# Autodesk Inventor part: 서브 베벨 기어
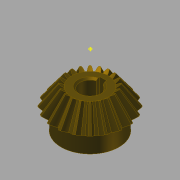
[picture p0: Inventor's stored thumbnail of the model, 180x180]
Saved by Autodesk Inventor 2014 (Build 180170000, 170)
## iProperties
Created: 2014-10
Part Number: 서브 베벨 기어
Material: 강철, 탄소
Document SubType Name: Modeling
Designer: KYOUNG IL JANG
Categories: <?xml version="1.0" encoding="UTF-16"?> <MemberInstance><Categories><FamilyTemplate><FamilyTemplateParameter ValueType="xs:double" Id="1" ObjectReferenceKey="da
Mass: 135.037 g
Surface Area: 63.6518 cm^2
Volume: 17.1585 cm^3
Density: 7.87 g/cm^3
Appearance: 얼룩무늬
CustomPartVersion: 1
Author: SeoGD™ [www.esajin.kr]
Revision Number: 1
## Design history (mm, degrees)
node "맨 위 점"
node "메쉬 평면2"
sketch "톱니 본체 스케치"
  geometry: L1 (0, 0)-(18.003, -31.331); L2 (18.003, -31.331)-(21.664, -28.891); L3 (21.664, -28.891)-(0, 0); L4 (20, -30)-(0, 0); L5 (10.813, -18.818)-(13.012, -17.352); L6 (18.003, -31.331)-(10.813, -18.818); L7 (21.664, -28.891)-(13.012, -17.352); L8 (0, -39.387)-(0, 6.564) reference; L9 (0, -30)-(21.664, -30)
  constraints: 16 end point, 4 point on line, 3 perpendicular, 2 collinear, 1 horizontal alignment, 1 vertical alignment
  dimensions: "d0" = 40 diameter of L4.start L8 (= da_de); "d1" = 36.00616 diameter of L1.end L8 (= da_dfe); "d2" = 43.3282 diameter of L2.end L8 (= da_dae); "d3" = 14.4 distance between parallel lines of L2 L5 (= da_b); "d4" = 28.8906 vertical distance of L2.end L1.start (= da_ve)
revolve "톱니 본체" sketch "톱니 본체 스케치" stored, may be unused: angle "d5" = 90 deg
node "시작점"
node "톱니 평면"
sketch "시작 스케치"
  geometry: L1 (0, -23.505)-(0, 10.645) reference; L2 (-0.834, -2.928)-(0.834, -2.928); A1 r 8.898 centre (-9.698, -3.713) between (-0.834, -2.928) and (-3.903, 3.04); A2 r 8.898 centre (9.698, -3.713) between (3.903, 3.04) and (0.834, -2.928); A3 r 27.357 centre (0, -24.037) between (3.903, 3.04) and (-3.903, 3.04); 1 further point
  constraints: 6 point on circle, 3 centre point, 3 symmetric about line, 2 end point, 1 coincident, 1 perpendicular, 1 other
  dimensions: "d7" = 8.89846 radius of A1 (= fd_rr); "d8" = 9.69794 horizontal distance of point (0, -24.037) A1.centre (= fd_x); "d9" = 20.32439 vertical distance of point (0, -24.037) A1.centre (= fd_y); "d57" = 27.35701 radius of A3 (= 0.5 x fd_dva + 0.3 x da_he); "d58" = 21.10901 distance from line of A3.centre L2 (= 0.5 x fd_dva - 1.12 x da_he)
node "끝점"
  node "끝 평면"
sketch "3D 스케치 오른쪽"
  node "Helical Curve Right" dims "d65" = 229.90621 (computed from da_dm, da_delta, da_beta), "d66" = 31.5, "d67" = 40 (= da_de), "d68" = -5.88003 (= -da_delta), "d69" = 12.16458 (computed from fd_loft, da_delta)
node "끝 평면 오른쪽"
sketch "끝 스케치 오른쪽"
  geometry: L1 (0, -22.649)-(0, 12.15) reference; L2 (-0.497, -1.72)-(0.497, -1.72); A1 r 5.299 centre (-5.775, -2.187) between (-0.497, -1.72) and (-2.324, 1.834); A2 r 5.299 centre (5.775, -2.187) between (2.324, 1.834) and (0.497, -1.72); A3 r 16.291 centre (0, -14.29) between (2.324, 1.834) and (-2.324, 1.834); 1 further point
  constraints: 6 point on circle, 3 centre point, 3 symmetric about line, 2 end point, 1 coincident, 1 perpendicular, 1 other
  dimensions: "d70" = 5.77526 horizontal distance of A3.centre A1.centre (computed from fd_x, fd_ratio); "d71" = 12.10346 vertical distance of point (0, -14.29) A1.centre (computed from fd_y, fd_ratio); "d72" = 5.29916 radius of A1 (computed from fd_rr, fd_ratio); "d73" = 12.57071 distance from line of point (0, -14.29) L2 (computed from d58, fd_ratio); "d74" = 16.29149 radius of A3 (computed from d57, fd_ratio)
feature "로프트 오른쪽" sketch "끝 스케치 오른쪽" dims "d75" = 0, "d77" = 0, "d79" = 0, "d80" = 90 deg, "d85" = 20, "d92" = 90 deg, "d93" = 90 deg, "da_teethtype" = 0 [user parameter]
sketch "3D 스케치 왼쪽"
  node "Helical Curve Left" dims "d26" = 229.90621 (computed from da_dm, da_delta, da_beta), "d27" = 12.16458 (computed from fd_loft, da_delta), "d28" = 40 (= da_de), "d29" = -5.88003 (= -da_delta)
node "끝 평면 왼쪽"
sketch "끝 스케치 왼쪽" dims "d56" = 10.82768 (derived)
  geometry: L1 (0, -35.087)-(0, 18.089) reference; L2 (-0.497, -1.716)-(0.497, -1.716); A1 r 5.299 centre (-5.775, -2.183) between (-0.497, -1.716) and (-2.324, 1.838); A2 r 5.299 centre (5.775, -2.183) between (2.324, 1.838) and (0.497, -1.716); A3 r 16.291 centre (0, -14.287) between (2.324, 1.838) and (-2.324, 1.838); 2 further points; 1 other entity
  constraints: 6 point on circle, 3 centre point, 3 symmetric about line, 2 end point, 1 coincident, 2 other
  dimensions: "d30" = 5.29916 radius of A1 (computed from fd_rr, fd_ratio); "d31" = 5.77526 horizontal distance of point (0, -14.287) A1.centre (computed from fd_x, fd_ratio); "d32" = 12.10346 vertical distance of A1.centre point (0, -14.287) (computed from fd_y, fd_ratio); "d61" = 16.29149 radius of A3 (computed from d57, fd_ratio); "d62" = 12.57071 distance from line of point (0, -14.287) L2 (computed from d58, fd_ratio)
feature "로프트 왼쪽" sketch "끝 스케치 왼쪽" dims "d35" = 0, "d37" = 0, "d39" = 0, "d40" = 90 deg, "d84" = 10, "d90" = 90 deg, "d91" = 90 deg, "da_teethtype" = 0 [user parameter]
sketch "본체 스케치"
  geometry: L1 (0, -35.038)-(0, -19.531) reference; L2 (18.003, -31.331)-(10.813, -18.818) reference; L3 (10.813, -18.818)-(0, -18.818); L4 (18.003, -31.331)-(0, -31.331)
  constraints: 4 end point, 2 perpendicular, 2 point on line
revolve "본체 고정" sketch "본체 스케치" stored, may be unused: angle "d46" = 90 deg
feature "피치 지름" dims angle "d47" = 90 deg
sketch "스케치8"
  geometry: C1 r 17 at (0, 0); 1 further point
  constraints: 1 centre point, 1 coincident
  dimensions: "d94" = 34 diameter of C1
extrude "돌출1" join sketch "스케치8" distance "d95" = 10; taper "d96" = 0 deg
sketch "스케치9"
  geometry: 1 further point
hole "구멍1" sketch "스케치9" at (0, 0) diameter "d97" = 12; stored, may be unused: countersink angle "d101" = 90 deg, drill point angle "d103" = 118 deg; dims "d98" = 6, "d99" = 4, "d100" = 2, "d102" = 8
sketch "스케치10"
  geometry: 1 further point
sketch "스케치11"
  geometry: 1 further point
sketch "스케치12"
  geometry: L1 (-2, 5.657)-(-2, 7.8); L2 (-2, 7.8)-(2, 7.8); L3 (2, 7.8)-(2, 5.657); A1 r 6 centre (0, 0) between (-2, 5.657) and (2, 5.657) reference; 1 further point
  constraints: 6 end point, 2 parallel, 2 point on circle, 1 perpendicular, 1 vertical
  dimensions: "d104" = 4 distance of L1.end L2.end; "d105" = 13.8 dimension on A1 L2
extrude "돌출2" cut sketch "스케치12" stored distance "d106" = 7; taper "d107" = 0 deg
chamfer "모따기1" distance "d108" = 1; stored, may be unused: second distance "d109" = 2, angle "d110" = 45 deg
body "Solid1"
feature "로프트" dims "d17" = 0, "d18" = 90 deg, "d19" = 0, "d20" = 90 deg, "d89" = 0, "da_teethtype" = 0 [user parameter]
pattern_circular "원형 패턴" dims angle "d22" = 360 deg, "d88" = 0, "da_teethtype" = 0 [user parameter]
pattern_circular "원형 패턴 오른쪽" dims angle "d82" = 360 deg, "da_teethtype" = 0 [user parameter]
pattern_circular "원형 패턴 왼쪽" dims angle "d42" = 360 deg, "da_teethtype" = 0 [user parameter]
sketch "끝 스케치"
  geometry: L1 (0, -15.359)-(0, 6.983) reference; L2 (-0.497, -1.72)-(0.497, -1.72); A1 r 5.299 centre (-5.775, -2.187) between (-0.497, -1.72) and (-2.324, 1.834); A2 r 5.299 centre (5.775, -2.187) between (2.324, 1.834) and (0.497, -1.72); A3 r 16.291 centre (0, -14.29) between (2.324, 1.834) and (-2.324, 1.834); 1 further point
  constraints: 6 point on circle, 3 centre point, 3 symmetric about line, 2 end point, 1 coincident, 1 other
  dimensions: "d12" = 5.29916 radius of A1 (computed from fd_rr, fd_ratio); "d15" = 5.77526 horizontal distance of A1.centre point (0, -14.29) (computed from fd_x, fd_ratio); "d16" = 12.10346 vertical distance of A1.centre point (0, -14.29) (computed from fd_y, fd_ratio); "d59" = 16.29149 radius of A3 (computed from d57, fd_ratio); "d60" = 12.57071 distance from line of A3.centre L2 (computed from d58, fd_ratio)
sketch "Sketch6"
  geometry: L1 (20, -30)-(0, 0) reference; L2 (0, -37.8)-(0, 6.3) reference
body "Srf1"
other parameters: "da_b" = 14.4 [user parameter; used in 2 equation terms], "da_de" = 40 [user parameter; used in 4 equation terms], "da_dae" = 43.3282 [user parameter; used in 2 equation terms], "da_dfe" = 36.00616 [user parameter; used in 1 equation term], "da_le" = 36.05551 [user parameter; used in 1 equation term], "da_omega" = 90 deg [user parameter; used in 1 equation term], "da_beta" = 0 [user parameter; used in 2 equation terms], "da_delta" = 5.88003 [user parameter; used in 8 equation terms], "da_alpha" = 20 deg [user parameter; used in 2 equation terms], "da_he" = 4.4 [user parameter; used in 4 equation terms], "da_ve" = 28.8906 [user parameter; used in 1 equation term], "fd_dv" = 48.07402 (computed from da_de, da_delta) [user parameter; used in 1 equation term], "fd_dva" = 52.07402 (computed from da_dae, da_delta) [user parameter; used in 3 equation terms], "fd_dvb" = 45.1748 (computed from fd_dv, da_alpha) [user parameter; used in 2 equation terms], "da_zv" = 240.37008 [user parameter; used in 1 equation term], "fd_loft" = 14.62 (= da_b + 0.05 x da_he) [user parameter; used in 4 equation terms], "fd_ratio" = 5.95514 (computed from da_le, fd_loft) [user parameter; used in 15 equation terms], "fd_rr" = 8.89846 (computed from fd_dd, fd_dvb) [user parameter; used in 6 equation terms], "fd_angle" = 0.66075 (computed from da_zv) [user parameter; used in 4 equation terms], "fd_x1" = 1.58709 (computed from da_dvw, fd_angle) [user parameter; used in 1 equation term], "fd_y1" = 23.98456 (computed from da_dvw, fd_angle) [user parameter; used in 1 equation term], "fd_x2" = 8.11084 (computed from fd_rr, fd_angle2, fd_angle) [user parameter; used in 1 equation term], "fd_y2" = 3.66016 (computed from fd_rr, fd_angle2, fd_angle) [user parameter; used in 1 equation term], "fd_x" = 9.69794 (= fd_x1 + fd_x2) [user parameter; used in 4 equation terms], "fd_y" = 20.32439 (= fd_y1 - fd_y2) [user parameter; used in 4 equation terms], "fd_angle2" = 3.57832 (computed from fd_dvb, fd_dd, da_alpha) [user parameter; used in 2 equation terms], "fd_dd" = 48.55402 (= fd_dva - 0.8 x da_he) [user parameter; used in 2 equation terms], "da_dvw" = 48.07402 [user parameter; used in 2 equation terms], "d11" = 14.62 (= fd_loft), "da_dm" = 32.01232 [user parameter; used in 2 equation terms], "da_x" = 0 [user parameter], "da_m" = 2 [user parameter], "d48" = 0, "d49" = 0, "d50" = 90 deg (= da_omega), "d51" = 9 deg (computed from da_z), "d52" = 0, "d53" = 0, "d54" = 0
